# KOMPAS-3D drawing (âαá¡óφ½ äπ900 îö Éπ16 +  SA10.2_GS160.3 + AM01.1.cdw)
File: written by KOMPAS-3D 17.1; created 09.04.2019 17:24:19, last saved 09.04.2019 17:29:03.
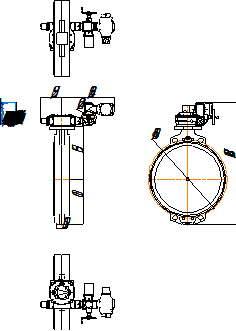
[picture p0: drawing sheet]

Sheet 1: A4, portrait

Title block, sheet 1: name: Гранвэл Ду900 МФ Ру16 + / SA10.2_GS160.3 + AM01.1; material: Внимание! Данный продукт является объектом авторского права ООО «Торговый Дом АДЛ». / Запрещается изменение, копирование, распространение / (в том числе путем копирования на другие сайты и ресурсы в Интернете) / или любое иное использование информации и объектов без предварительного / согласия правообладателя (ООО «Торговый Дом АДЛ»).; mass: 1031,77; sheets: 1; organisation: ООО "Торговый дом АДЛ"; sheet format: A4

Views: Вид 1, Спереди, Проекционный вид 2, Проекционный вид 3
Referenced files in \\adlc.lan\data\АДЛ_ПКД\3D-модели\ADL production\Дисковые поворотные затворы ГРАНВЭЛ\межфланцевый с эл.приводом Auma Ру 16\KOMPAS 3D\: Гранвэл Ду900 МФ Ру16 + SA10.2_GS160.3 + AM01.1.m3d
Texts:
  user
Dimensions and other numbers on the sheet: 695; 610; 150; 692,34; 289,5; 200; 1:1; 1; 1031,77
